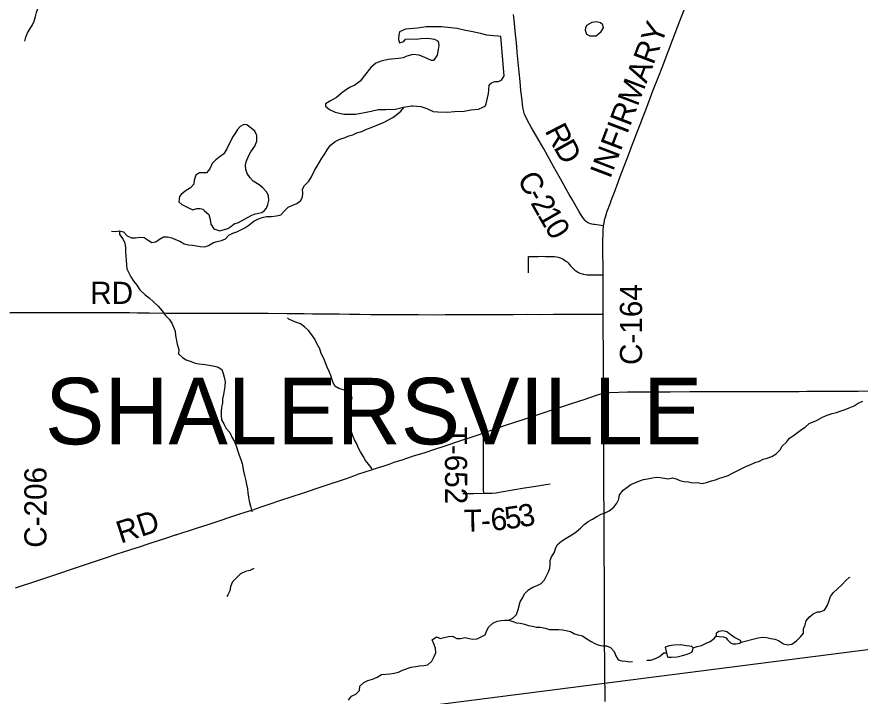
# Model space of a CAD drawing. Extents: x 0 to 34, y 0 to 22.
# Drawn here: x 5.549 to 7.711, y 18.065 to 19.806 of the extents above; entities that cross this region are included whole.
import ezdxf

# ---------------------------------------------------------------- set-up
doc = ezdxf.new("R2010")
doc.units = 0
for name, color, linetype in [('GM_X_County_Road', 7, 'Continuous'), ('GM_X_County_Road_Text', 7, 'Continuous'), ('GM_X_Minor_Lake', 7, 'Continuous'), ('GM_X_Minor_River', 7, 'Continuous'), ('GM_X_Township_Road', 7, 'Continuous'), ('GM_X_Township_Road_Text', 7, 'Continuous'), ('GM_X_Township_Text', 7, 'Continuous'), ('SH_Text', 7, 'Continuous')]:
    doc.layers.add(name, color=color, linetype=linetype)

msp = doc.modelspace()

# ---------------------------------------------------------------- linework, layer by layer
at = {"layer": 'GM_X_County_Road'}
for points in [[(7.0536, 19.271), (7.0541, 19.2743), (7.0547, 19.2783), (7.0554, 19.2828), (7.0562, 19.2865), (7.0574, 19.2906), (7.0591, 19.2966), (7.0609, 19.3021), (7.063, 19.3081), (7.0652, 19.3141), (7.0678, 19.3212), (7.0709, 19.3296), (7.073, 19.3352), (7.0812, 19.357), (7.091, 19.3827), (7.0963, 19.3969), (7.1065, 19.4232), (7.1156, 19.4471), (7.1253, 19.4729), (7.1338, 19.4952), (7.1422, 19.5175), (7.1487, 19.5348), (7.1547, 19.5507), (7.1615, 19.5681), (7.1731, 19.5981), (7.18, 19.6162), (7.194, 19.6527), (7.2033, 19.6765), (7.218, 19.7144), (7.2305, 19.7467), (7.244, 19.7821), (7.2525, 19.8044), (7.2601, 19.8244)], [(7.0536, 19.271), (7.0474, 19.2715), (7.0422, 19.272), (7.0358, 19.2729), (7.0311, 19.2736), (7.0272, 19.2743), (7.0232, 19.2752), (7.0195, 19.2761), (7.0154, 19.2776), (7.012, 19.2794), (7.0094, 19.2811), (7.0061, 19.2841), (7.0019, 19.2892), (6.9982, 19.2942), (6.9951, 19.2995), (6.9902, 19.3079), (6.9718, 19.3401), (6.9654, 19.3512), (6.9579, 19.3646), (6.9515, 19.376), (6.9429, 19.3911), (6.9327, 19.4092), (6.925, 19.423), (6.9095, 19.4512), (6.9001, 19.468), (6.8884, 19.4884), (6.8791, 19.5046), (6.8742, 19.513), (6.8681, 19.5233), (6.8585, 19.5406), (6.8523, 19.5532), (6.8502, 19.5583), (6.8487, 19.5638), (6.8472, 19.5704), (6.8463, 19.5758), (6.8455, 19.5818), (6.8445, 19.591), (6.8429, 19.6054), (6.8416, 19.6178), (6.8392, 19.6405), (6.8371, 19.6644), (6.8322, 19.7161), (6.8309, 19.7308), (6.8292, 19.7475), (6.8276, 19.7618), (6.8258, 19.7799), (6.824, 19.7982), (6.8225, 19.8124)], [(7.0521, 19.1453), (7.052, 19.1689), (7.0519, 19.1996), (7.0518, 19.219), (7.0518, 19.2286), (7.0519, 19.2383), (7.052, 19.2448), (7.0522, 19.2523), (7.0524, 19.2575), (7.0527, 19.2625), (7.0531, 19.2665), (7.0536, 19.271)], [(7.0525, 19.0446), (7.0524, 19.0817), (7.0522, 19.1254), (7.0521, 19.1453)], [(7.0534, 18.8414), (7.0533, 18.8657), (7.053, 18.9137), (7.0529, 18.9497), (7.0526, 19.0074), (7.0525, 19.031), (7.0525, 19.0446)], [(6.745, 18.7396), (6.7527, 18.7426), (6.7686, 18.7481), (6.7998, 18.7587), (6.8231, 18.7663), (6.8475, 18.7744), (6.8809, 18.7855), (6.9116, 18.7957), (6.9376, 18.8043), (6.9659, 18.8134), (7.006, 18.8267), (7.0326, 18.8356), (7.0435, 18.839), (7.0494, 18.8405), (7.0534, 18.8414)], [(7.0534, 18.8414), (7.0576, 18.8422), (7.063, 18.8429), (7.0695, 18.8434), (7.115, 18.8448), (7.1436, 18.8451), (7.1672, 18.8452), (7.2244, 18.8453), (7.2747, 18.8459), (7.3008, 18.846), (7.3406, 18.846), (7.3829, 18.8461), (7.4139, 18.846), (7.4443, 18.8462), (7.4567, 18.8461), (7.4846, 18.8461), (7.5207, 18.8463), (7.5549, 18.8464), (7.5748, 18.8467), (7.5983, 18.8467), (7.6369, 18.8467), (7.6555, 18.8467), (7.6822, 18.8469), (7.7064, 18.8473), (7.735, 18.8477)], [(7.0574, 18.0516), (7.0572, 18.0766), (7.0568, 18.1097), (7.0565, 18.1427), (7.0564, 18.1609), (7.0562, 18.1947), (7.056, 18.2191), (7.0557, 18.2495), (7.0556, 18.2829), (7.0555, 18.31), (7.0554, 18.385), (7.0553, 18.4123), (7.0551, 18.4668), (7.0548, 18.5147), (7.0546, 18.5472), (7.0544, 18.5826), (7.0542, 18.6323), (7.054, 18.6601), (7.0539, 18.6961), (7.0537, 18.7194), (7.0536, 18.7417), (7.0535, 18.7727), (7.0534, 18.8166), (7.0534, 18.8414)], [(5.5459, 18.3425), (5.6054, 18.3624), (5.639, 18.3738), (5.7074, 18.3966), (5.7511, 18.4109), (5.7717, 18.4179), (5.8094, 18.4305), (5.8206, 18.4342), (5.8437, 18.4417), (5.8638, 18.4482), (5.8863, 18.4554), (5.9205, 18.4667), (5.9288, 18.4693), (5.9557, 18.4783), (5.9575, 18.4789), (5.9598, 18.4796), (5.9645, 18.4811), (5.9704, 18.483), (5.9721, 18.4835), (5.9779, 18.4852), (5.9897, 18.489), (6.0128, 18.4965), (6.0399, 18.5055), (6.0652, 18.5138), (6.0982, 18.5248), (6.1182, 18.5315), (6.1347, 18.5369), (6.1543, 18.5431), (6.1732, 18.5493), (6.1991, 18.558), (6.2238, 18.5664), (6.2549, 18.5769), (6.2814, 18.5858), (6.3345, 18.6035), (6.394, 18.6233), (6.4128, 18.6299), (6.4263, 18.6346), (6.4422, 18.64), (6.4587, 18.6454), (6.4764, 18.6511), (6.4912, 18.6559), (6.5042, 18.6601), (6.5165, 18.6646), (6.5371, 18.6713), (6.5518, 18.6763), (6.566, 18.6808), (6.5933, 18.6892), (6.621, 18.6985), (6.6446, 18.7062), (6.6871, 18.7202), (6.7059, 18.7264), (6.7195, 18.7311), (6.745, 18.7396)]]:
    msp.add_lwpolyline(points, dxfattribs=at)
at = {"layer": 'GM_X_Minor_Lake'}
for p, q in [((7.0229, 19.7915), (7.0097, 19.7838)), ((6.7983, 19.6547), (6.7904, 19.7559)), ((6.1173, 19.279), (6.152, 19.2982)), ((7.3605, 18.2177), (7.3673, 18.2147)), ((7.2115, 18.1911), (7.2166, 18.1684))]:
    msp.add_line(p, q, dxfattribs=at)
for points in [[(6.7904, 19.7559), (6.7828, 19.7566), (6.771, 19.7577), (6.754, 19.7595), (6.7377, 19.7639), (6.7142, 19.7683), (6.6998, 19.7716), (6.6785, 19.7767), (6.6376, 19.7802), (6.5987, 19.7803), (6.576, 19.7775), (6.5453, 19.7742), (6.5303, 19.7676), (6.5288, 19.76), (6.5281, 19.7483), (6.5305, 19.7396), (6.541, 19.743), (6.5459, 19.7488), (6.558, 19.7496), (6.5735, 19.7486), (6.5853, 19.751), (6.6027, 19.7515), (6.6201, 19.7493), (6.6292, 19.7437), (6.6308, 19.7327), (6.6298, 19.7229), (6.6265, 19.7084), (6.6175, 19.6947), (6.6122, 19.6943), (6.5955, 19.7017), (6.5803, 19.7081), (6.5648, 19.7095), (6.5489, 19.7056), (6.5395, 19.7013), (6.5277, 19.6993), (6.5009, 19.6968), (6.4835, 19.6925), (6.4699, 19.6871), (6.4564, 19.6764), (6.4403, 19.6562), (6.4294, 19.6417), (6.4159, 19.6313), (6.4023, 19.6252), (6.3914, 19.6171), (6.382, 19.6106), (6.3684, 19.5999), (6.353, 19.5906), (6.3402, 19.5833), (6.341, 19.5769), (6.3509, 19.569), (6.3657, 19.5623), (6.3877, 19.5568), (6.4179, 19.557), (6.4402, 19.5613), (6.4573, 19.5645), (6.4754, 19.5684), (6.4951, 19.569), (6.5197, 19.5692), (6.5404, 19.5743), (6.5612, 19.5782), (6.5643, 19.5782), (6.5847, 19.5765), (6.6006, 19.5717), (6.6162, 19.5635), (6.6287, 19.5628), (6.6529, 19.5618), (6.6715, 19.5635), (6.6961, 19.5648), (6.7135, 19.568), (6.7327, 19.5696), (6.7437, 19.575), (6.7497, 19.5777), (6.7523, 19.5831), (6.7556, 19.5983), (6.7582, 19.6097), (6.7592, 19.6184), (6.7599, 19.6317), (6.7663, 19.6367), (6.775, 19.6401), (6.7837, 19.6406), (6.7893, 19.6433), (6.7923, 19.646), (6.7961, 19.6505), (6.7983, 19.6547)], [(7.0097, 19.7838), (7.0071, 19.7777), (7.006, 19.772), (7.0095, 19.7618), (7.0186, 19.7577), (7.0341, 19.7574), (7.0401, 19.7624), (7.0476, 19.7685), (7.0529, 19.7781), (7.0517, 19.7856), (7.0452, 19.7905), (7.035, 19.7938), (7.0229, 19.7915)], [(6.152, 19.2982), (6.1603, 19.3017), (6.1693, 19.3033), (6.1773, 19.3048), (6.184, 19.3102), (6.1897, 19.3159), (6.193, 19.3251), (6.1956, 19.3353), (6.1943, 19.3486), (6.1897, 19.3576), (6.1802, 19.3678), (6.1703, 19.3753), (6.1555, 19.3851), (6.1478, 19.3934), (6.1402, 19.4047), (6.1363, 19.4149), (6.1358, 19.4259), (6.1369, 19.4346), (6.1429, 19.4491), (6.1496, 19.4605), (6.1593, 19.475), (6.1649, 19.4876), (6.1644, 19.502), (6.159, 19.5133), (6.1457, 19.5246), (6.1385, 19.5295), (6.1313, 19.5302), (6.1215, 19.5252), (6.1147, 19.5175), (6.1084, 19.5065), (6.1035, 19.5), (6.0942, 19.4828), (6.0878, 19.4676), (6.08, 19.455), (6.0706, 19.4485), (6.0597, 19.4401), (6.0503, 19.4305), (6.0439, 19.4165), (6.0357, 19.4065), (6.0175, 19.4064), (6.0085, 19.4006), (6.004, 19.3877), (6.003, 19.3778), (5.9944, 19.3683), (5.9812, 19.3591), (5.9703, 19.3507), (5.9665, 19.3461), (5.9647, 19.3317), (5.972, 19.3256), (5.9876, 19.3174), (6.0001, 19.3114), (6.0107, 19.3146), (6.0194, 19.3146), (6.0262, 19.3132), (6.0308, 19.3094), (6.0418, 19.2996), (6.0453, 19.2871), (6.0469, 19.2746), (6.0546, 19.2633), (6.0694, 19.2574), (6.0902, 19.264), (6.0977, 19.2689), (6.1063, 19.2758), (6.1173, 19.279)], [(7.3673, 18.2147), (7.3715, 18.2094), (7.3784, 18.2023), (7.3844, 18.1993), (7.3931, 18.1997), (7.4018, 18.2013), (7.4064, 18.2032), (7.4044, 18.2078), (7.3889, 18.2153), (7.3801, 18.2216), (7.3698, 18.2299), (7.3592, 18.2329), (7.349, 18.2313), (7.3422, 18.2255), (7.3423, 18.2191), (7.3495, 18.2184), (7.3605, 18.2177)], [(7.2166, 18.1684), (7.2182, 18.1654), (7.2208, 18.165), (7.2276, 18.1651), (7.2424, 18.166), (7.2556, 18.1695), (7.2651, 18.1722), (7.2745, 18.1753), (7.2794, 18.178), (7.2813, 18.1807), (7.2835, 18.189), (7.28, 18.1924), (7.266, 18.1946), (7.2505, 18.1964), (7.2338, 18.1959), (7.2217, 18.1943), (7.2115, 18.1911)]]:
    msp.add_lwpolyline(points, dxfattribs=at)
at = {"layer": 'GM_X_Minor_River'}
for points in [[(5.5698, 19.744), (5.5728, 19.7542), (5.5769, 19.7653), (5.5825, 19.7748), (5.5892, 19.7858), (5.594, 19.7954), (5.5974, 19.8075), (5.5995, 19.8174), (5.6029, 19.8277), (5.6073, 19.8379), (5.6133, 19.8479), (5.6242, 19.8586), (5.6343, 19.8696), (5.6445, 19.8769), (5.6566, 19.8842), (5.6671, 19.8926), (5.6788, 19.8988), (5.6889, 19.9053), (5.701, 19.9122), (5.7202, 19.9317), (5.7273, 19.9417), (5.734, 19.9512), (5.7351, 19.9554)], [(5.792, 19.2571), (5.8022, 19.2564), (5.8124, 19.2577), (5.8226, 19.2551), (5.8318, 19.2453), (5.8432, 19.2397), (5.8538, 19.2398), (5.8651, 19.2414), (5.8757, 19.2407), (5.886, 19.2336), (5.8955, 19.2276), (5.9053, 19.2299), (5.9151, 19.2364), (5.9257, 19.2426), (5.9355, 19.2427), (5.9469, 19.2397), (5.9564, 19.236), (5.9674, 19.2312), (5.9784, 19.2244), (5.9894, 19.2222), (5.9993, 19.2208), (6.0095, 19.2197), (6.0194, 19.2175), (6.0311, 19.2169), (6.0409, 19.22), (6.0533, 19.2276), (6.0632, 19.2308), (6.0737, 19.2331), (6.0839, 19.237), (6.0929, 19.2469), (6.1031, 19.2519), (6.1129, 19.255), (6.1239, 19.26), (6.1337, 19.2654), (6.1442, 19.272), (6.1566, 19.2823), (6.1687, 19.2885), (6.1785, 19.2923), (6.1895, 19.2943), (6.2023, 19.2944), (6.2152, 19.2964), (6.2265, 19.2988), (6.2359, 19.3091), (6.2449, 19.3186), (6.2566, 19.3236), (6.2672, 19.3279), (6.2773, 19.3352), (6.2818, 19.3447), (6.2825, 19.3542), (6.2813, 19.3648), (6.2865, 19.3743), (6.2978, 19.385), (6.3045, 19.3965), (6.3123, 19.4128), (6.3191, 19.4235), (6.325, 19.4334), (6.3314, 19.4437), (6.3392, 19.4551), (6.3452, 19.4654), (6.3538, 19.4772), (6.3655, 19.4864), (6.3772, 19.4926), (6.3908, 19.4969), (6.4006, 19.5011), (6.4108, 19.5042), (6.421, 19.5089), (6.4334, 19.5127), (6.444, 19.5174), (6.4576, 19.5224), (6.4678, 19.5267), (6.4791, 19.5313), (6.4912, 19.5359), (6.5021, 19.5425), (6.513, 19.5486), (6.5236, 19.5559), (6.5341, 19.5643), (6.5426, 19.5747)], [(5.8124, 19.2577), (5.8129, 19.2482), (5.8209, 19.2369), (5.8263, 19.2259), (5.8275, 19.2153), (5.8283, 19.2043), (5.8288, 19.1937), (5.8293, 19.1816), (5.8305, 19.1706), (5.8317, 19.16), (5.8363, 19.1501), (5.8417, 19.1403), (5.8494, 19.1282), (5.8566, 19.1184), (5.865, 19.1063), (5.8784, 19.0939), (5.8887, 19.0857), (5.8997, 19.0755), (5.9119, 19.065), (5.9215, 19.0529), (5.9306, 19.0412), (5.9398, 19.0311), (5.9463, 19.0212), (5.9509, 19.0107), (5.9556, 19.0005), (5.9564, 18.9898), (5.9604, 18.9671), (5.9642, 18.9535), (5.9636, 18.9429), (5.9739, 18.9335), (5.9837, 18.9275), (5.9959, 18.9226), (6.0069, 18.9189), (6.0171, 18.9167), (6.0323, 18.9149), (6.0421, 18.9135), (6.0558, 18.9113), (6.0653, 18.908), (6.0752, 18.9024), (6.0783, 18.8925), (6.0806, 18.8827), (6.083, 18.8713), (6.0823, 18.8592), (6.0812, 18.8486), (6.0791, 18.8383), (6.0769, 18.8269), (6.0762, 18.8163), (6.0736, 18.8056), (6.073, 18.7946), (6.0727, 18.7848), (6.0743, 18.7734), (6.08, 18.7632), (6.0858, 18.7515), (6.0953, 18.7413), (6.1015, 18.7277), (6.1069, 18.7179), (6.1123, 18.7039), (6.1161, 18.6929), (6.1192, 18.6831), (6.1239, 18.6714), (6.127, 18.6615), (6.1302, 18.6418), (6.1333, 18.6305), (6.136, 18.6172), (6.1384, 18.6074), (6.1403, 18.5968), (6.1419, 18.5862), (6.1428, 18.5756), (6.1451, 18.565), (6.1486, 18.5521), (6.151, 18.5419), (6.1518, 18.5377)], [(6.4605, 18.6481), (6.451, 18.6595), (6.4433, 18.6693), (6.4372, 18.6802), (6.4303, 18.6915), (6.4241, 18.7021), (6.421, 18.7123), (6.4149, 18.7225), (6.411, 18.7324), (6.4072, 18.7426), (6.4003, 18.7531), (6.3938, 18.7641), (6.3914, 18.7751), (6.394, 18.7857), (6.3977, 18.796), (6.4029, 18.8074), (6.4055, 18.8192), (6.4088, 18.8298), (6.4045, 18.84), (6.3958, 18.8498), (6.3855, 18.8501), (6.3749, 18.8538), (6.3646, 18.8594), (6.3593, 18.8704), (6.3542, 18.8874), (6.3503, 18.8976), (6.3446, 18.9082), (6.3403, 18.9192), (6.3361, 18.9309), (6.3296, 18.9434), (6.3257, 18.9551), (6.3192, 18.9672), (6.313, 18.98), (6.3057, 18.9914), (6.2973, 19.0027), (6.2878, 19.0106), (6.2767, 19.0192), (6.2661, 19.0229), (6.2562, 19.0274), (6.2468, 19.0311), (6.2433, 19.0345)], [(7.5991, 18.7718), (7.6146, 18.78), (7.6266, 18.7854), (7.6395, 18.7898), (7.6501, 18.7922), (7.6625, 18.7969), (7.6727, 18.8), (7.6832, 18.8043), (7.6957, 18.8094), (7.7062, 18.8164), (7.7179, 18.8211)], [(7.2817, 18.6116), (7.2935, 18.6124), (7.3063, 18.6106), (7.3173, 18.613), (7.3298, 18.6169), (7.3407, 18.62), (7.3509, 18.6242), (7.3622, 18.6273), (7.3732, 18.6305), (7.3837, 18.6366), (7.3962, 18.6424), (7.4082, 18.6485), (7.4199, 18.6543), (7.4309, 18.6586), (7.4418, 18.6644), (7.4528, 18.6675), (7.4629, 18.6725), (7.4728, 18.6752), (7.4848, 18.6795), (7.4958, 18.686), (7.5059, 18.6967), (7.5115, 18.7062), (7.5224, 18.7158), (7.5299, 18.7265), (7.5401, 18.7334), (7.5506, 18.741), (7.5608, 18.7483), (7.5705, 18.7545), (7.5807, 18.7644), (7.5991, 18.7718)], [(6.3992, 18.0552), (6.4071, 18.0655), (6.418, 18.0702), (6.4278, 18.0801), (6.4289, 18.0907), (6.439, 18.0999), (6.4492, 18.1053), (6.4613, 18.1092), (6.473, 18.1142), (6.4843, 18.1204), (6.4956, 18.122), (6.5054, 18.1224), (6.5164, 18.1244), (6.5277, 18.1271), (6.5379, 18.1318), (6.5606, 18.1395), (6.5715, 18.1415), (6.5817, 18.1431), (6.5927, 18.1439), (6.6029, 18.1459), (6.6131, 18.1547), (6.6194, 18.1665), (6.6235, 18.1764), (6.6223, 18.1885), (6.618, 18.1991), (6.6138, 18.2093), (6.6255, 18.217), (6.6349, 18.2133), (6.6451, 18.2156), (6.6557, 18.2184), (6.6663, 18.2192), (6.677, 18.2129), (6.6868, 18.2129), (6.6989, 18.2153), (6.7091, 18.2131), (6.7186, 18.2113), (6.7296, 18.2121), (6.7499, 18.2225), (6.754, 18.2335), (6.7592, 18.2431), (6.7694, 18.2523), (6.7803, 18.2573), (6.7905, 18.2592), (6.8004, 18.2601), (6.8106, 18.2601), (6.8204, 18.2652), (6.8301, 18.2747), (6.8342, 18.2873), (6.8394, 18.307), (6.8461, 18.3177), (6.8509, 18.3272), (6.8611, 18.3375), (6.872, 18.3448), (6.8833, 18.3487), (6.8935, 18.3537), (6.9017, 18.3636), (6.9073, 18.3739), (6.9126, 18.3838), (6.9159, 18.3933), (6.9162, 18.4032), (6.9165, 18.4127), (6.9195, 18.4226), (6.9266, 18.4329), (6.9303, 18.4424), (6.9347, 18.453), (6.9464, 18.4637), (6.9622, 18.4726), (6.972, 18.4791), (6.9829, 18.486), (6.9946, 18.4956), (7.004, 18.5051), (7.0138, 18.5128), (7.0247, 18.5189), (7.036, 18.5255), (7.0473, 18.5316), (7.0579, 18.5351), (7.0681, 18.5401), (7.0797, 18.5497), (7.0876, 18.5596), (7.0924, 18.5703), (7.0942, 18.5809), (7.1036, 18.5935), (7.1134, 18.6004), (7.1236, 18.6073), (7.1337, 18.6123), (7.1439, 18.6166), (7.156, 18.6205), (7.1658, 18.6224), (7.1787, 18.6248), (7.1885, 18.6268), (7.1984, 18.6257), (7.209, 18.6243), (7.2188, 18.6221), (7.2302, 18.6248), (7.2396, 18.6222), (7.2491, 18.6181), (7.259, 18.6152), (7.2715, 18.6141), (7.2817, 18.6116)], [(6.1571, 18.3925), (6.1465, 18.3875), (6.1355, 18.3847), (6.1227, 18.3785), (6.1024, 18.3579), (6.0969, 18.3461), (6.095, 18.3355), (6.0906, 18.3252), (6.088, 18.321)], [(7.6077, 18.2817), (7.6197, 18.286), (7.6275, 18.2986), (7.6319, 18.3108), (7.6352, 18.3207), (7.6431, 18.3307), (7.6528, 18.3407), (7.6648, 18.3511), (7.6742, 18.3618), (7.6839, 18.3703), (7.6839, 18.3695)], [(7.4064, 18.2032), (7.4498, 18.215), (7.4608, 18.2166), (7.4717, 18.2155), (7.482, 18.2133), (7.4926, 18.2115), (7.5021, 18.2081), (7.515, 18.1991), (7.5256, 18.1966), (7.5358, 18.1989), (7.5483, 18.207), (7.5584, 18.2173), (7.5659, 18.2268), (7.5658, 18.2378), (7.5699, 18.2481), (7.5725, 18.258), (7.5807, 18.2675), (7.5905, 18.2763), (7.6014, 18.2817), (7.6077, 18.2817)], [(6.8106, 18.2601), (6.8208, 18.2564), (6.8303, 18.2535), (6.8402, 18.252), (6.8504, 18.2495), (6.8606, 18.2465), (6.8713, 18.2447), (6.8815, 18.2417), (6.8921, 18.2422), (6.9035, 18.2396), (6.9145, 18.2359), (6.9266, 18.2364), (6.9379, 18.2365), (6.9482, 18.2354), (6.9576, 18.2336), (6.969, 18.2306), (6.9789, 18.2254), (6.9884, 18.2228), (6.9998, 18.2195), (7.0108, 18.2124), (7.0214, 18.2056), (7.0309, 18.2004), (7.0412, 18.1963), (7.0514, 18.1945), (7.0613, 18.1942), (7.0708, 18.1901), (7.0803, 18.1799), (7.0849, 18.1682), (7.0907, 18.1584), (7.1002, 18.1562), (7.1108, 18.1551), (7.1206, 18.1533), (7.1278, 18.1537)], [(7.2835, 18.189), (7.2933, 18.1925), (7.3042, 18.1953), (7.3167, 18.2007), (7.3269, 18.2049), (7.337, 18.2126), (7.3423, 18.2191)], [(7.1645, 18.1578), (7.1743, 18.1575), (7.1868, 18.1614), (7.1966, 18.1668), (7.2079, 18.1759), (7.2149, 18.176)]]:
    msp.add_lwpolyline(points, dxfattribs=at)
at = {"layer": 'GM_X_Township_Road'}
for points in [[(6.8609, 19.1503), (6.8608, 19.1532), (6.8607, 19.1658), (6.8607, 19.1739), (6.8608, 19.1823), (6.8607, 19.189), (6.8609, 19.192)], [(6.8609, 19.192), (6.8635, 19.1923), (6.8658, 19.1922), (6.8783, 19.1924), (6.886, 19.1923), (6.8961, 19.1925), (6.9047, 19.1923), (6.9172, 19.1924), (6.9221, 19.1923), (6.9276, 19.192), (6.9331, 19.1913), (6.9369, 19.1904), (6.94, 19.1895), (6.9425, 19.1885), (6.9468, 19.1868), (6.9501, 19.1851), (6.956, 19.1812), (6.9584, 19.1794), (6.96, 19.178), (6.9627, 19.1754), (6.9655, 19.1724), (6.969, 19.1683), (6.9739, 19.1627), (6.9761, 19.1603), (6.9797, 19.1573), (6.9822, 19.1553), (6.9868, 19.1524), (6.989, 19.1512), (6.9924, 19.1496), (6.9992, 19.1473), (7.0016, 19.1468), (7.0062, 19.1458), (7.0116, 19.1454), (7.0166, 19.1453), (7.0279, 19.1453), (7.0396, 19.1454), (7.0479, 19.1453), (7.0511, 19.1453), (7.0521, 19.1453)], [(5.5311, 19.0488), (5.5677, 19.0485), (5.5937, 19.0485), (5.6049, 19.0485), (5.6341, 19.0485), (5.6583, 19.0485), (5.6962, 19.0482), (5.7111, 19.0482), (5.7247, 19.0481), (5.7464, 19.0482), (5.7725, 19.0481), (5.8048, 19.0481), (5.8384, 19.0482), (5.8589, 19.0478), (5.8893, 19.0475), (5.9328, 19.047), (5.9571, 19.0471), (5.9919, 19.0471), (6.0161, 19.0468), (6.0683, 19.0467), (6.1038, 19.047), (6.1939, 19.0466), (6.2411, 19.046), (6.2859, 19.0457), (6.3076, 19.0453), (6.3486, 19.0453), (6.3698, 19.0452), (6.376, 19.0451), (6.4021, 19.0444), (6.4282, 19.0439), (6.4561, 19.0435), (6.4825, 19.0434), (6.5156, 19.0435), (6.5461, 19.0434), (6.579, 19.0431), (6.6163, 19.0428), (6.6473, 19.0431), (6.6786, 19.043), (6.7114, 19.043), (6.7446, 19.0435), (6.7779, 19.0436), (6.8227, 19.0435), (6.8586, 19.0438), (6.8896, 19.0435), (6.9253, 19.044), (6.957, 19.0441), (6.97, 19.044), (6.9811, 19.044), (6.9998, 19.0439), (7.0423, 19.0445), (7.0525, 19.0446)], [(6.7461, 18.5853), (6.746, 18.5929), (6.7459, 18.5979), (6.7457, 18.6457), (6.7456, 18.6836), (6.7454, 18.7184), (6.745, 18.7396)], [(6.7461, 18.5853), (6.7542, 18.5854), (6.7679, 18.5858), (6.7784, 18.5867), (6.7907, 18.5886), (6.8508, 18.5989), (6.8796, 18.6038), (6.9054, 18.608), (6.9164, 18.6098)], [(6.6927, 18.5843), (6.72, 18.5849), (6.7461, 18.5853)]]:
    msp.add_lwpolyline(points, dxfattribs=at)
at = {"layer": 'SH_Text'}
msp.add_lwpolyline([(9.3865, 18.3957), (4.9237, 17.8249), (9.3865, 18.0457)], close=True, dxfattribs=at)

# ---------------------------------------------------------------- texts
at = {"layer": 'GM_X_County_Road_Text'}
for s, height, rotation, p in [('INFIRMARY', 0.05682, 69.1728, (7.0702, 19.3893)), ('R', 0.0568, 297.2737, (6.9018, 19.5146)), ('D', 0.0568, 299.0802, (6.9241, 19.4715)), ('C', 0.0568, 299.3746, (6.8307, 19.3906)), ('2', 0.0568, 299.5001, (6.8651, 19.3294)), ('-', 0.0568, 299.4117, (6.8536, 19.3499)), ('1', 0.0568, 299.8827, (6.8826, 19.2986)), ('0', 0.0568, 301.1303, (6.9007, 19.2671)), ('C-164', 0.05682, 90, (7.1521, 18.914)), ('C-206', 0.05682, 90, (5.6254, 18.4456)), ('RD', 0.05682, 18.1207, (5.8156, 18.4561))]:
    msp.add_text(s, height=height, rotation=rotation, dxfattribs=at).set_placement(p)
at = {"layer": 'GM_X_Township_Road_Text'}
for s, height, rotation, p in [('RD', 0.05682, 0, (5.7376, 19.0705)), ('T-652', 0.05682, 270.2823, (6.6464, 18.7556)), ('6', 0.0568, 5.8438, (6.7665, 18.4886)), ('5', 0.0568, 8.2952, (6.8039, 18.4925)), ('3', 0.0568, 9.228, (6.8395, 18.4977)), ('T', 0.0568, 0.9858, (6.6954, 18.4862)), ('-', 0.0568, 3.3098, (6.7404, 18.487))]:
    msp.add_text(s, height=height, rotation=rotation, dxfattribs=at).set_placement(p)
at = {"layer": 'GM_X_Township_Text'}
msp.add_text('SHALERSVILLE', height=0.170455, rotation=0, dxfattribs=at).set_placement((5.6215, 18.7106))

doc.saveas('drawing.dxf')
